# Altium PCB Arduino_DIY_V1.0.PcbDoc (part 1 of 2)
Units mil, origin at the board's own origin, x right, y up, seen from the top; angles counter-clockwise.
Board outline 4006.09 x 4935.69 mil, 2 copper layers (Top Layer, Bottom Layer), stack 46.063 mil thick; 121 components, 93 nets, 429 pads, 83 vias.
Unrouted connection lines stored in the file: 78.
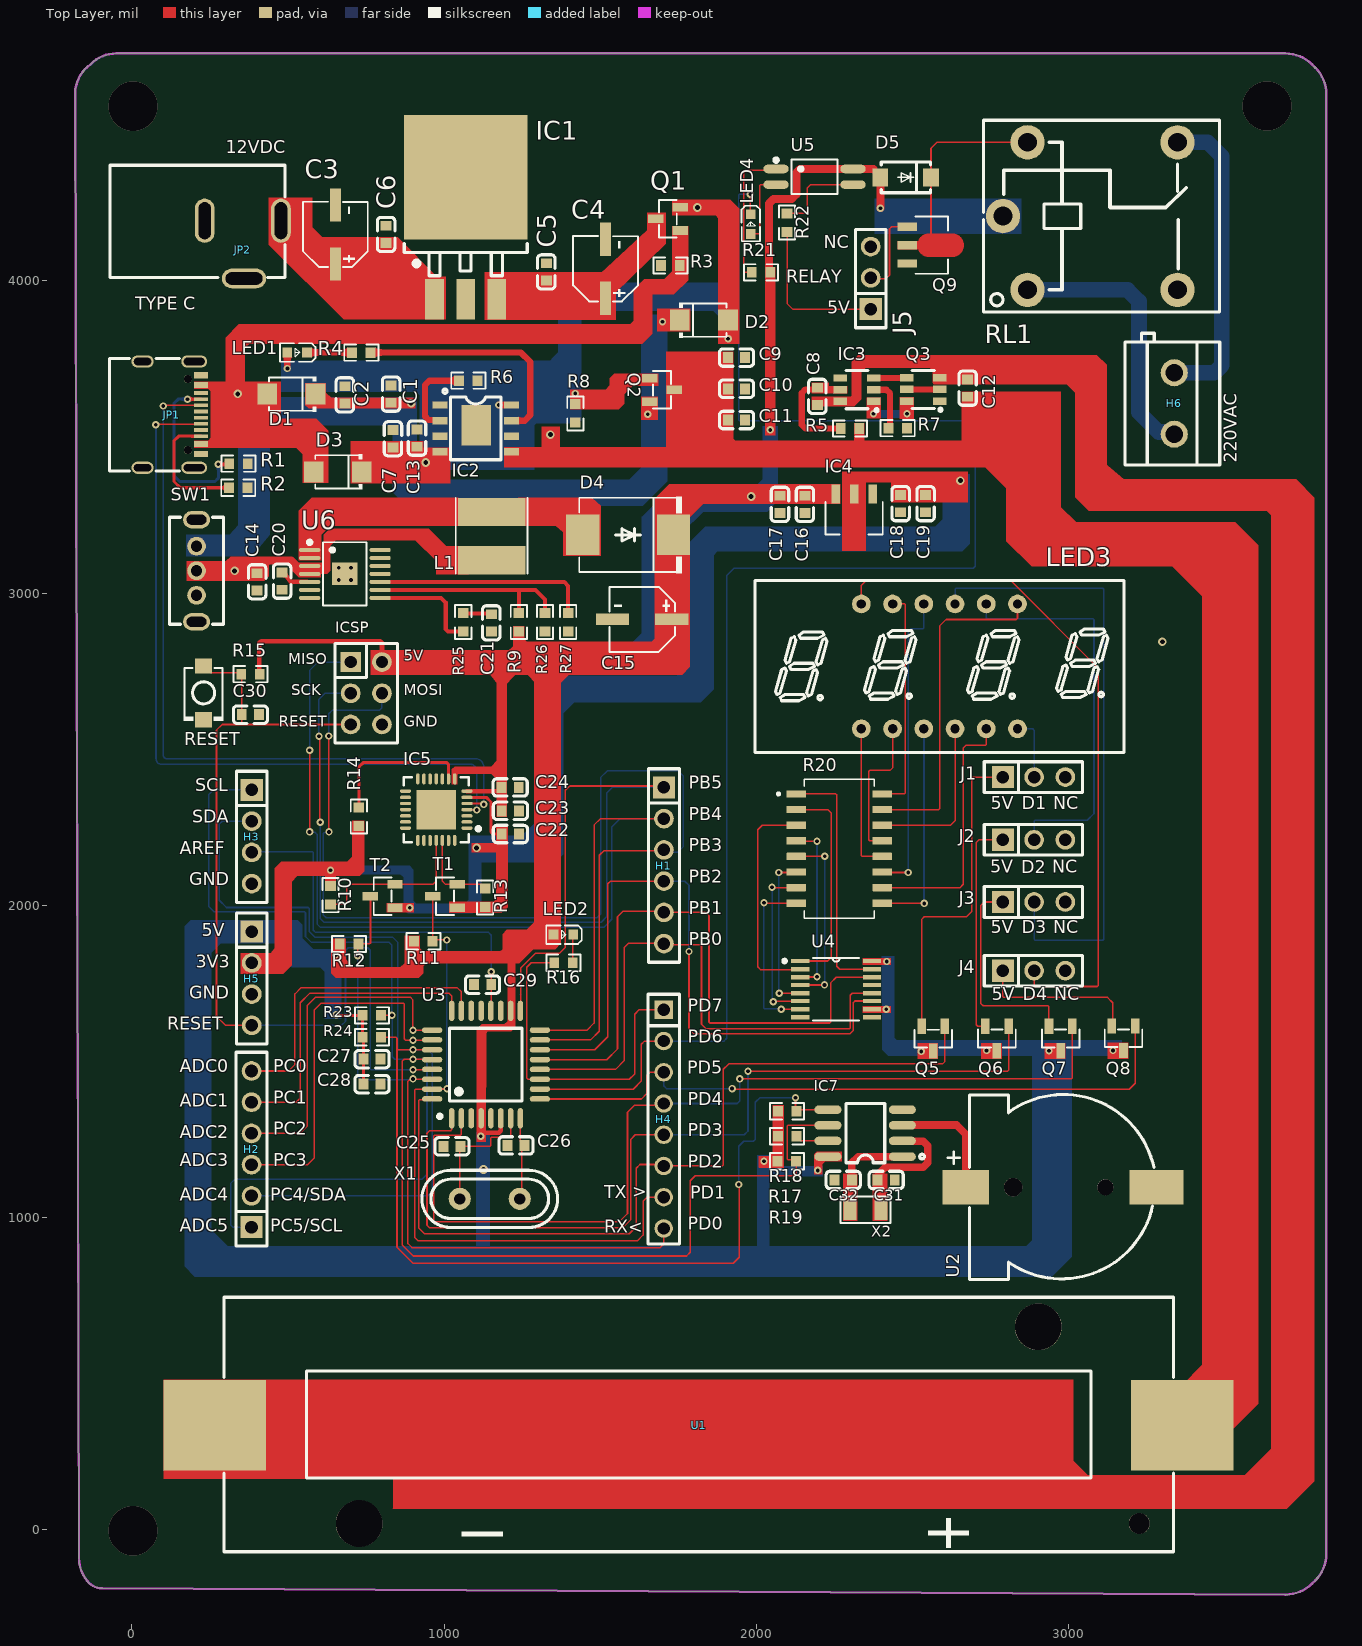
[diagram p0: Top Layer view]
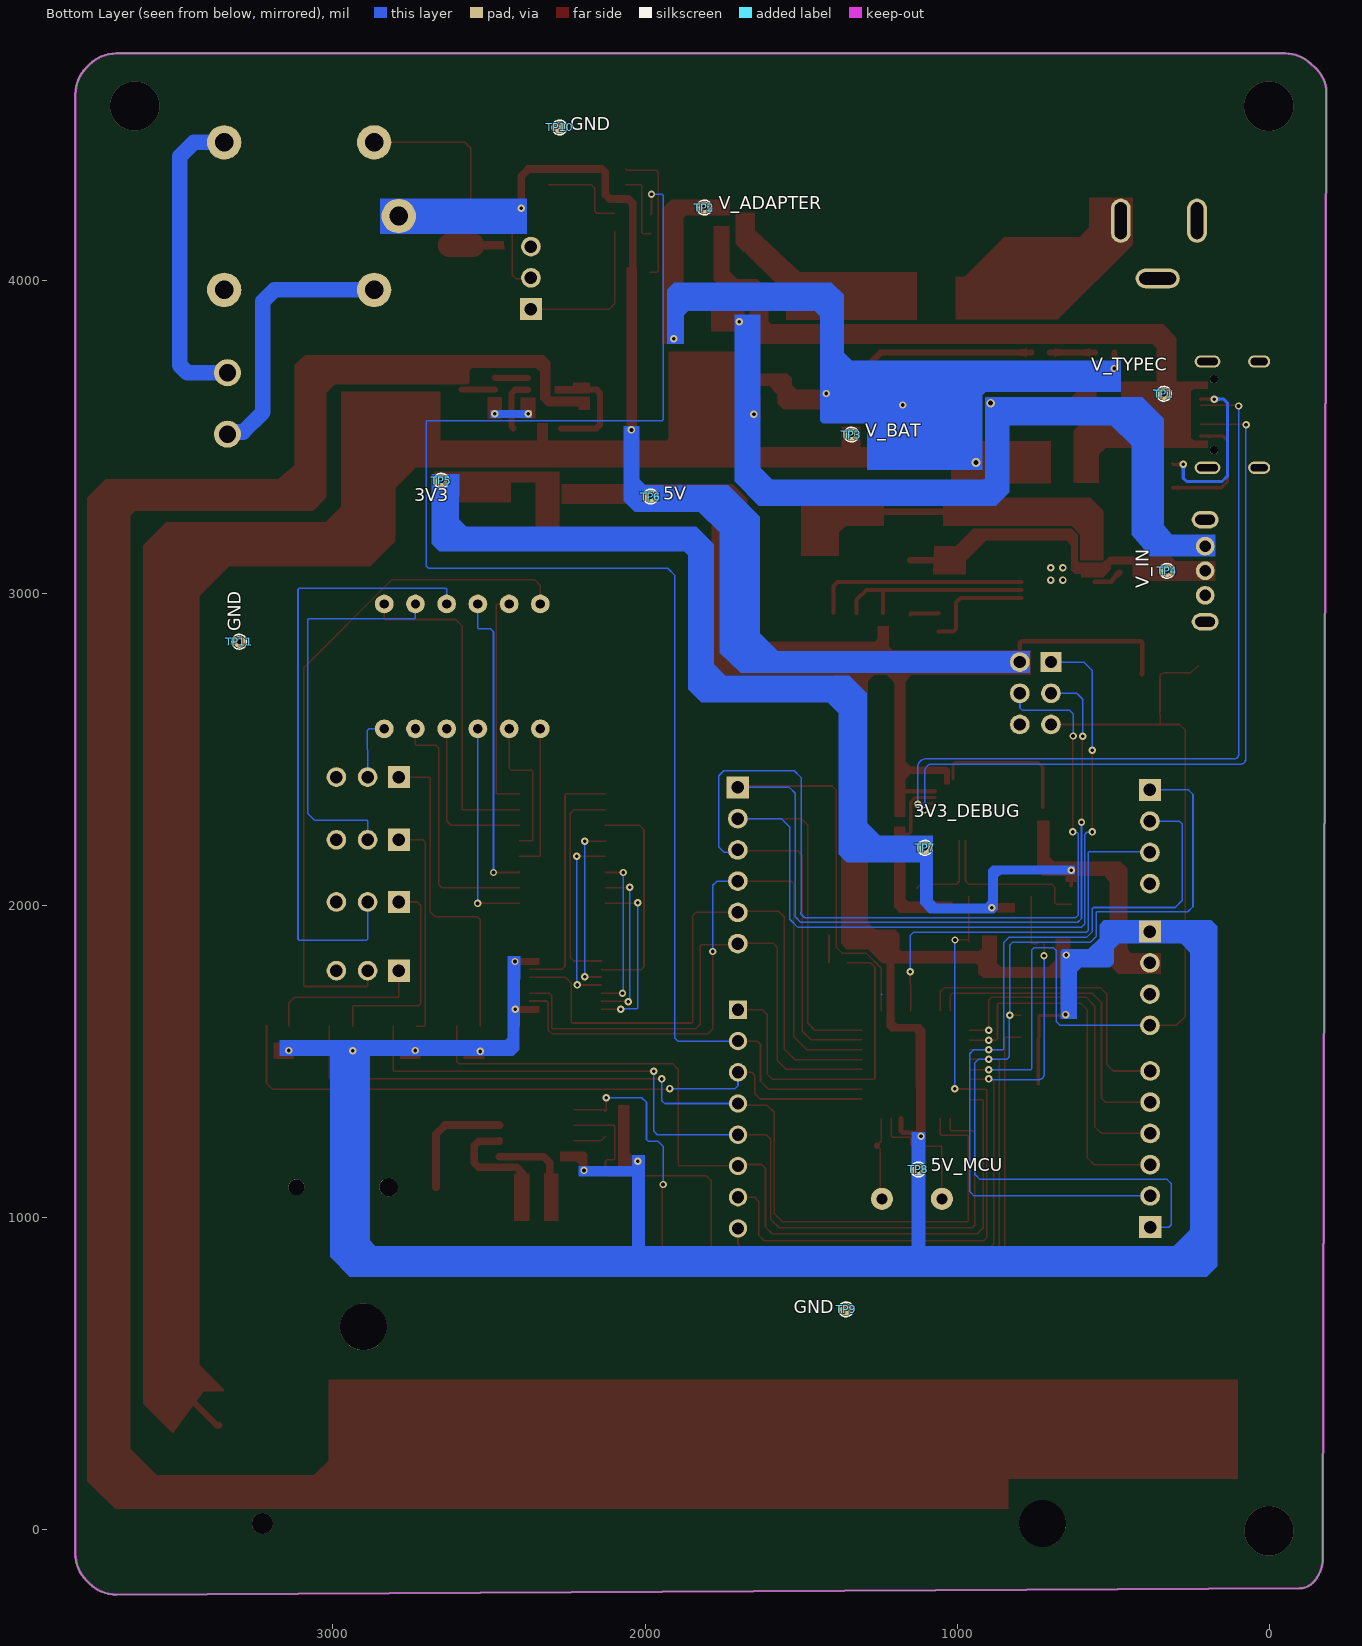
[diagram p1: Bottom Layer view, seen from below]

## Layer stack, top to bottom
Top Solder: solder mask 0.5, Solder Resist, Dk 3.8
Top Layer: signal copper 1.378
Dielectric 1: dielectric 43.307, FR-4, Dk 4.5
Bottom Layer: signal copper 1.378
Bottom Solder: solder mask 0.5, Solder Resist, Dk 3.8

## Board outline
-136.76,-170.5 ccw(c-95.74,-129.48) -95.74,-187.49 3694.03,-207.52 ccw(c3694.03,-86.81) 3779.38,-172.17 3789.67,-161.88 ccw(c3704.32,-76.52) 3825.03,-76.52 3825,-75.9 3825,4597 ccw(c3704.29,4597) 3789.65,4682.35 3779.35,4692.65 ccw(c3694,4607.29) 3694,4728 3608.61,4728 3608.61,4728.17 -49.9,4728.17 ccw(c-49.9,4613.53) -130.96,4694.59 -133.61,4692.28 ccw(c-63.14,4595.96) -181.06,4614.33 -169.44,-91.6 ccw(c-57.87,-91.6)

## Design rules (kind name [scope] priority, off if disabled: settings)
BoardOutlineClearance [All] p1: gap=7.87 ignorepadtopadclearanceinfootprint=FALSE
Clearance [All] p1: gap=5 ignorepadtopadclearanceinfootprint=FALSE except(9.84: Arc-Hole Track-Hole SMDPad-Hole THPad-Hole Via-Hole Fill-Hole Poly-Hole Region-Hole Text-Hole)
ComponentClearance [All] p1: gap=5 collisioncheckmode=3 verticalgap=5 showdistances=TRUE
DiffPairsRouting [All] p1: maxlimit=10 minlimit=5 mostfreqgap=5 toplayer_minwidth=5 toplayer_maxwidth=1000 toplayer_prefwidth=5 bottomlayer_minwidth=5 bottomlayer_maxwidth=1000 bottomlayer_prefwidth=5 maxuncoupledlength=500
Height [All] p1: minheight=0 maxheight=71497.94 prefheight=500
HoleSize [All] p1: absolutevalues=TRUE maxlimit=248.03 minlimit=11.81 maxpercent=80.000 minpercent=20.000
HoleToHoleClearance [All] p1: gap=9.84 allowstackedmicrovias=FALSE
MinimumAnnularRing [All] p1: minimumring=3
MinimumSolderMaskSliver [All] p1: minsoldermaskwidth=0
PlaneClearance [All] p1: clearance=5
PlaneConnect PlaneConnectPowerPads [InPadClass('PowerPads')] p1: planeconnectstyle=Direct reliefexpansion=20 reliefentries=4 reliefconductorwidth=10 reliefairgap=10
PlaneConnect [All] p2: pad.planeconnectstyle=Relief pad.reliefexpansion=11.81 pad.reliefentries=4 pad.reliefconductorwidth=5 pad.reliefairgap=5 via.planeconnectstyle=Direct via.reliefexpansion=11.81 via.reliefentries=4 via.reliefconductorwidth=5 via.reliefairgap=5
PolygonConnect PolygonConnectPowerPads [All vs (InPadClass('PowerPads'))] p1: connectstyle=Direct reliefconductorwidth=10 reliefentries=4 polygonreliefangle="90 Angle" airgapwidth=10
PolygonConnect [All] p2: thpad.connectstyle=Relief thpad.reliefconductorwidth=5 thpad.reliefentries=4 thpad.polygonreliefangle="90 Angle" thpad.airgapwidth=5 smdpad.connectstyle=Relief smdpad.reliefconductorwidth=5 smdpad.reliefentries=4 smdpad.polygonreliefangle="90 Angle" smdpad.airgapwidth=5 via.connectstyle=Direct via.reliefconductorwidth=5 via.reliefentries=4 via.polygonreliefangle="90 Angle" via.airgapwidth=5
RoutingVias [All] p1: holewidth=11.81 width=23.62 viastyle="Through Hole" minholewidth=11.81 minwidth=23.62 maxholewidth=23.62 maxwidth=259.84
SilkToSilkClearance [All] p1: silktosilkclearance=0
SilkToSolderMaskClearance [IsPad] p1: minsilkscreentomaskgap=5 clearancetoexposedcopper=TRUE
SolderMaskExpansion [All] p1: expansion=2.95 istentingtop=FALSE
Width [All] p1: maxlimit=1000 minlimit=5 preferedwidth=5 minimp=50.000000 maximp=50.000000 favimp=50.000000
20 further rules are at their usual default settings.

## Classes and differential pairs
component class "VOLTAGE SOURCE": C1 C2 C3 C4 C5 C6 C7 C8 C9 C10 C11 C12 C13 C14 C15 C16 C17 C18 C19 C20 C21 D1 D2 D3 D4 IC1 IC2 IC3 IC4 JP1 JP2 L1 LED1 Q1 Q2 Q3 R1 R2 R3 R4 R5 R6 R7 R8 R9 R25 R26 R27 SW1 TP1 TP2 TP3 TP4 TP5 TP6 TP9 TP10 TP11 U1 U6 V_IN
component class Peripheral: C31 C32 D5 H1 H2 H3 H4 H5 H6 IC7 ICSP J1 J2 J3 J4 J5 LED3 LED4 Q5 Q6 Q7 Q8 Q9 R17 R18 R19 R20 R21 R22 R23 R24 RL1 U2 U4 U5 X2
component class MCU: C22 C23 C24 C25 C26 C27 C28 C29 C30 IC5 LED2 R10 R11 R12 R13 R14 R15 R16 RESET T1 T2 TP7 TP8 U3 X1

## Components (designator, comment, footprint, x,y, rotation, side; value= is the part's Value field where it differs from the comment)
C1 "100nF" C0603 830,3637 r270 top
C2 "22uF" C0603 681.99,3634.51 r270 top
C3 "47uF, 25V" CAP_ALU_C 652,4148.35 r90 top
C4 "47uF, 25V" CAP_ALU_C 1517,4038.35 r90 top
C5 "100nF" C0603 1327,4028.35 r270 top
C6 "330nF" C0603 814,4148.35 r270 top
C7 "100nF" C0603 836,3494 r270 top
C8 "100nF" C0603 2195,3630 r90 top
C9 "100nF" C0603 1936.22,3753.96 r180 top
C10 "10uF" C0603 1936.22,3653.96 r180 top
C11 "22uF" C0603 1936.22,3553.96 r180 top
C12 "10uF" C0603 2676,3656 r270 top
C13 "10uF" C0603 913,3496 r270 top
C14 "22uF" C0603 401,3036 r90 top
C15 "47uF, 25V" CAP_ALU_C 1634,2916 r180 top
C16 "10uF" C0603 2155.35,3284 r90 top
C17 "22uF" C0603 2075.35,3284 r90 top
C18 "10uF" C0603 2461.65,3286 r90 top
C19 "22uF" C0603 2541.65,3286 r90 top
C20 "47nF" C0603 481,3038 r90 top
C21 "33nF" C0603 1151,2904.5 r90 top
C22 "100nF" C0603 1212,2228.35 r180 top
C23 "100nF" C0603 1212,2302.35 r180 top
C24 "1uF" C0603 1211.44,2377.35 r180 top
C25 "33pF" C0603 1025,1228 r180 top
C26 "33pF" C0603 1230,1231 r180 top
C27 "10uF" C0603 769,1507.35 r180 top
C28 "10nF" C0603 769,1427.35 r180 top
C29 "100nF" C0603 1123,1746 r0 top
C30 "10pF" C0603 379.5,2610.35 r0 top
C31 "33pF" C0603 2415.55,1120.35 r0 top
C32 "33pF" C0603 2278,1120.35 r180 top
D1 "S3MF" D_SMAF_L3.5-W2.6-LS4.7-RD 511,3637 r180 top
D2 "S3MF" D_SMAF_L3.5-W2.6-LS4.7-RD 1832,3874 r0 top
D3 "S3MF" D_SMAF_L3.5-W2.6-LS4.7-RD 659,3388 r180 top
D4 "SS54" SMC 1589,3186 r180 top
D5 "1N4007_M7" SMA(DO-214AC) 2478,4331 r0 top
H1 "6P 2.54mm Female Header" "6P, 2,54mm, FEMALE HEADER" 1703.79,2127.35 r270 top
H2 "6P 2.54mm Female Header" "6P, 2,54mm, FEMALE HEADER" 383,1219.35 r90 top
H3 "4P 2.54mm Female Header" "4P, 2,54mm, FEMALE HEADER" 383.79,2219.35 r270 top
H4 "8P 2.54mm Female Header" "8P, 2,54mm, FEMALE HEADER" 1703,1315.24 r270 top
H5 "4P 2.54mm Female Header" "4P, 2,54mm, FEMALE HEADER" 383.79,1765.52 r270 top
H6 "KF301-5.0-2P" CONN-TH_P5.00_KF301-5.0-2P 3338,3607 r90 top
IC1 "LM7805" TO-263-3L 1071,4332.26 r90 top
IC2 "TP4056" ESOP-8 1102,3525 r270 top
IC3 "DW01A" SOT-23-6 2322,3651 r90 top
IC4 "AMS1117-3.3" SOT-89-3L 2313,3317 r90 top
IC5 "CP2102" WQFN-28-EP(5x5) 974.58,2306.31 r180 top
IC7 "DS1307" SOIC-8 2348,1270.35 r180 top
ICSP "2x3P 2.54mm Female Header" "2x3P, 2.54mm, Female Header" 750.72,2679 r0 top
J1 "JUMPER_SHUNT_3P" JUMPER_SHUNT_3P 2789.16,2410.56 r0 top
J2 "JUMPER_SHUNT_3P" JUMPER_SHUNT_3P 2789.16,2209.78 r0 top
J3 "JUMPER_SHUNT_3P" JUMPER_SHUNT_3P 2789.16,2010.56 r0 top
J4 "JUMPER_SHUNT_3P" JUMPER_SHUNT_3P 2789.16,1790.56 r0 top
J5 "JUMPER_SHUNT_3P" JUMPER_SHUNT_3P 2366,3909.35 r90 top
JP1 "TYPE_C_16P, Female" TYPE_C_16P 128,3571.35 r270 top
JP2 "DC_POWER_JACK" DC_POWER_JACK_6.3mm_2.1mm 233.15,4192.35 r0 top
L1 "4.7uH 3.1A" CD54 1152,3180 r270 top
LED1 "Red" LED0603_RED 529,3770.35 r0 top
LED2 "Blue" LED0603_BLUE 1381.69,1906.04 r0 top
LED3 "LED7SEG" LED7SEG_4 2586,2765 r0 top
LED4 "Green" LED0603_GREEN 1982,4181.35 r90 top
Q1 "AO3401" TF_SOT_23_3 1676.75,4198.35 r90 top
Q2 "AO3401" TF_SOT_23_3 1736.99,3650.4 r270 top
Q3 "FS8205A" TF_SOT23-6 2587.31,3614.6 r180 top
Q5 "ZXTN2031FTA" SOT-23 2566.16,1572.93 r90 top
Q6 "ZXTN2031FTA" SOT-23 2770.16,1573.56 r90 top
Q7 "ZXTN2031FTA" SOT-23 2974.16,1573.56 r90 top
Q8 "ZXTN2031FTA" SOT-23 3175.56,1574.19 r90 top
Q9 "2N2222" SOT-89-3L 2483,4114.06 r180 top
R1 "5.1kΩ" R0603 395.88,3440.36 r180 top
R2 "5.1kΩ" R0603 395.19,3363.01 r180 top
R3 "10kΩ" R0603 1670.12,4022.99 r0 top
R4 "10kΩ" R0603 680.12,3743.99 r0 top
R5 "100Ω" R0603 2245.12,3500.99 r0 top
R6 "2kΩ" R0603 1131.88,3706.01 r180 top
R7 "1kΩ" R0603 2506.88,3554.01 r180 top
R8 "10kΩ" R0603 1446.01,3520.81 r90 top
R9 "49.9kΩ" R0603 1213,2961.22 r270 top
R10 "10kΩ" R0603 662.01,1977.81 r90 top
R11 "10kΩ" R0603 987.88,1911.01 r180 top
R12 "10kΩ" R0603 749.88,1902.01 r180 top
R13 "10kΩ" R0603 1104.99,2079.23 r270 top
R14 "1kΩ" R0603 700.99,2338.54 r270 top
R15 "10kΩ" R0603 325.31,2714.34 r0 top
R16 "330Ω" R0603 1327.51,1790.04 r0 top
R17 "4.7kΩ" R0603 2152.88,1286.36 r180 top
R18 "4.7kΩ" R0603 2152.88,1366.36 r180 top
R19 "4.7kΩ" R0603 2152.19,1206.36 r180 top
R20 "RES_ARRAY_8_RES_330Ω" SOIC-16-5.6mm 2265.16,2181.56 r0 top
R21 "330Ω" R0603 1960.12,4000.99 r0 top
R22 "2kΩ" R0603 2071.99,4240.88 r270 top
R23 "4.7kΩ" R0603 823.19,1673.36 r180 top
R24 "4.7kΩ" R0603 823.19,1603.36 r180 top
R25 "2.55kΩ" R0603 1034.99,2961.22 r270 top
R26 "16.2kΩ" R0603 1349.02,2852.16 r90 top
R27 "133KΩ" R0603 1423.01,2852.16 r90 top
RESET "SMD 3mm×4mm" "ROUND_BUTTON_SMD 3*4mm" 229.5,2680.35 r270 top
RL1 "SRD-05VDC-SL-C" "Through Hole,15.6x19.2mm" 3069,4207 r0 top
SW1 "SK12D07VG4" SK12D07VG4 207,3234.74 r270 top
T1 "BS170F" SOT-23 1003,2029.35 r0 top
T2 "BS170F" SOT-23 803,2029.35 r0 top
TP1 "Test Point" TEST_POINT 339,3638 r90 bottom
TP2 "Test Point" TEST_POINT 1810.82,4234.53 r90 bottom
TP3 "Test Point" TEST_POINT 1340,3507.35 r90 bottom
TP4 "Test Point" TEST_POINT 329,3071 r90 bottom
TP5 "Test Point" TEST_POINT 2653,3360 r180 bottom
TP6 "Test Point" TEST_POINT 1983,3309 r90 bottom
TP7 "Test Point" TEST_POINT 1104,2184 r0 bottom
TP8 "Test Point" TEST_POINT 1126,1154 r270 bottom
TP9 "Test Point" TEST_POINT 1357,706 r90 bottom
TP10 "Test Point" TEST_POINT 2274.58,4490.96 r90 bottom
TP11 "Test Point" TEST_POINT 3300,2844 r180 bottom
U1 "Battery Holder 18650 SMD" PIN_18650_1S_HOLDER_SMD 1815,335 r180 top
U2 "3V_COIN_BATTERY_HOLDER" 3V_COIN_BATERRY_HOLDER_CR1220 2975.54,1097 r180 top
U3 "ATMEGA328P-AU" "TQFP-32 (7x7)" 1134,1490 r90 top
U4 "74HC595" TSSOP16 2255.16,1731.56 r0 top
U5 "TLP291" SO-4 2186,4333 r0 top
U6 "TPS61175PWPR" HTSSOP-14-EP 682,3061 r270 top
X1 "16MHz" HC-49S 1146,1060 r180 top
X2 "32.768kHz" SMD3215-2P 2349,1025 r0 top

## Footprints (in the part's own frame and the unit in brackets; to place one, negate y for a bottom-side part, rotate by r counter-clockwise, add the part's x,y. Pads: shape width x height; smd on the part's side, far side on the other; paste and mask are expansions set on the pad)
"2x3P, 2.54mm, Female Header" [mm]
  rect 1.7x1.6 hole 1 paste-2539.97 mask+0.051: 1(-1.27,2.54)
  round 1.6 hole 1 paste-2539.97 mask+0.051: 2(-1.27,0) 3(-1.27,-2.54) 4(1.27,-2.54) 5(1.27,0) 6(1.27,2.54)
  silkscreen extent -2.54,-4.04 2.54,4.04, body extent -2.5,-4.06 2.5,4.06, height 8.5
3V_COIN_BATERRY_HOLDER_CR1220 [mm]
  rect 3.75x2.8 smd paste+0 mask+0.051: 1(7.75,0)
  rect 4.4x2.8 smd paste+0 mask+0.051: 2(-7.75,0)
  round 1.3 hole 1.3 unplated paste-2539.97: ""(-3.6,0)
  round 1.5 hole 1.5 unplated paste-2539.97: ""(3.9,0)
  silkscreen extent -7.55,-7.54 9.22,7.49, body extent -9.78,-7.4 9.42,7.35, height 4.25
"4P, 2,54mm, FEMALE HEADER" [mm]
  rect 1.8x1.8 hole 1.02 paste-2539.97 mask+0.051: 1(-3.81,0)
  round 1.6 hole 1.02 paste-2539.97 mask+0.051: 2(-1.27,0) 3(1.27,0) 4(3.81,0)
  silkscreen extent -5.33,-1.25 5.33,1.25, body extent -5.08,-1.25 5.08,1.25, height 8.5
"6P, 2,54mm, FEMALE HEADER" [mm]
  rect 1.8x1.8 hole 1.02 paste-2539.97 mask+0.051: 1(-6.35,0)
  round 1.6 hole 1.02 paste-2539.97 mask+0.051: 2(-3.81,0) 3(-1.27,0) 4(1.27,0) 5(3.81,0) 6(6.35,0)
  silkscreen extent -7.87,-1.25 7.87,1.25, body extent -7.62,-1.25 7.62,1.25, height 8.5
"8P, 2,54mm, FEMALE HEADER" [mm]
  rect 1.5x1.5 hole 1 paste-2539.97 mask+0.051: 1(-8.89,0)
  round 1.5 hole 1 paste-2539.97 mask+0.051: 2(-6.35,0) 3(-3.81,0) 4(-1.27,0) 5(1.27,0) 6(3.81,0) 7(6.35,0) 8(8.89,0)
  silkscreen extent -10.16,-1.27 10.16,1.27, body extent -10.16,-1.25 10.16,1.25, height 8.5
C0603 [mm]
  rect 0.8x0.9 smd paste+0 mask+0.051: 1(-0.7,0) 2(0.7,0)
  silkscreen extent -1.39,-0.71 1.39,0.71, body extent -0.8,-0.39 0.8,0.41, height 0.8
CAP_ALU_C [mm]
  rect 2.7x0.91 smd paste+0 mask+0.051: 1(-2.4,0) 2(2.4,0)
  silkscreen extent -2.66,-2.62 2.66,2.65, body extent -3.25,-2.76 3.25,2.76, height 6.15
CD54 [mil]
  rect 90x216.53 smd paste-3937.01 mask+1.97: 1(75,0) 2(-80,0)
  silkscreen extent -124,-115 118,115, body extent -114,-102 114,102, height 177
CONN-TH_P5.00_KF301-5.0-2P [mm]
  round 2.2 hole 1.4 paste-2539.97 mask+0.051: 1(-2.5,0) 2(2.5,0)
  silkscreen extent -5,-3.7 5.71,4, body extent -5,-3.55 5,4.05, height 10
D_SMAF_L3.5-W2.6-LS4.7-RD [mm]
  rect 1.6x1.7 smd paste+0 mask+0.051: 1(-1.96,0.001) 2(1.96,0.001)
  silkscreen extent -2.01,-1.43 1.83,1.42, body extent -2.65,-1.27 2.65,1.27, height 1
DC_POWER_JACK_6.3mm_2.1mm [mm]
  oval 1.6x3.6 hole 1 slot 3 at 90 deg paste-2539.97 mask+0.051: 1(6.2,0) 2(0,0)
  oval 3.6x1.6 hole 1 slot 3 at 0 deg paste-2539.97 mask+0.051: 3(3.2,-4.7)
  silkscreen extent -7.7,-4.64 6.52,4.51, body extent -7.72,-4.95 6.48,4.45, height 11.09
ESOP-8 [mm]
  rect 0.6x1.2 smd paste+0 mask+0.051: 1(-1.956,-2.934) 2(-0.686,-2.934) 3(0.584,-2.934) 4(1.854,-2.934) 5(1.854,2.883) 6(0.584,2.883) 7(-0.686,2.883) 8(-1.956,2.883)
  rect 3.3x2.4 smd paste+0 mask+0.051: 9(-0.305,0)
  silkscreen extent -3.25,-2.7 2.5,2.02, body extent -2.55,-3.1 2.45,3.1, height 1.82
HC-49S [mm]
  round 1.8 hole 0.9 paste+0 mask+0.051: 1(-2.44,0) 2(2.44,0)
  silkscreen extent -5.52,-2.32 5.52,2.33, body extent -5.83,-2.67 5.83,2.67, height 3.99
HTSSOP-14-EP [mm]
  oval 0.343x1.731 smd paste+0 mask+0.051: 1(-1.95,-2.866) 2(-1.3,-2.866) 3(-0.65,-2.866) 4(0,-2.866) 5(0.65,-2.866) 6(1.3,-2.866) 7(1.95,-2.866) 8(1.95,2.866) 9(1.3,2.866) 10(0.65,2.866) 11(0,2.866) 12(-0.65,2.866) 13(-1.3,2.866) 14(-1.95,2.866)
  rect 1.83x2.055 smd paste+0 mask+0.051: 15(0,0)
  silkscreen extent -2.72,-3.02 2.58,1.77, body extent -2.5,-3.2 2.5,3.2, height 1.2
JUMPER_SHUNT_3P [mm]
  rect 1.8x1.8 hole 1.02 paste-2539.97 mask+0.051: 1(0,0)
  round 1.6 hole 1.02 paste-2539.97 mask+0.051: 2(2.54,0) 3(5.08,0)
  silkscreen extent -1.52,-1.25 6.48,1.25, body extent -1.27,-1.27 6.41,1.27, height 8.6
LED7SEG_4 [mil]
  round 60 hole 30: 1(-250,-200) 2(-150,-200) 3(-50,-200) 4(50,-200) 5(150,-200) 6(250,-200) 7(250,200) 8(150,200) 9(50,200) 10(-50,200) 11(-150,200) 12(-250,200)
  silkscreen extent -591,-276 591,276, body extent -591,-276 591,276, height 423
LED0603_BLUE [mm]
  rect 0.8x0.8 smd paste+0 mask+0.051: 1(-0.799,0) 2(0.799,0)
  silkscreen extent -1.39,-0.76 1.49,0.75, body extent -0.8,-0.4 0.8,0.4, height 0.6
LED0603_GREEN [mm]
  rect 0.8x0.8 smd paste+0 mask+0.051: 1(-0.799,0) 2(0.799,0)
  silkscreen extent -1.39,-0.76 1.49,0.75, body extent -0.8,-0.4 0.8,0.4, height 0.6
LED0603_RED [mm]
  rect 0.8x0.8 smd paste+0 mask+0.051: 1(-0.799,0) 2(0.799,0)
  silkscreen extent -1.39,-0.76 1.49,0.75, body extent -0.8,-0.4 0.8,0.4, height 0.6
PIN_18650_1S_HOLDER_SMD [mm]
  rect 8.34x7.35 smd paste+0 mask+0.051: 1(-39.345,0) 2(39.345,0)
  round 1.7 hole 1.7 unplated paste-2539.97: ""(-35.84,8)
  round 3.8 hole 3.8 unplated paste-2539.97: ""(-27.62,-8) ""(27.62,8)
  silkscreen extent -38.61,-10.41 38.61,10.29, body extent -43.22,-10.4 43.22,10.4, height 17.46
R0603 [mil]
  rect 31.75x34.02 smd paste+0 mask+2: 1(24.88,26.01) 2(84.19,26.01)
  silkscreen extent 0,0 109,52, body extent 24,10 86,42, height 18
"ROUND_BUTTON_SMD 3*4mm" [mm]
  rect 1.23x1.36 smd paste+0 mask+0.051: 1(-2.185,0) 2(2.185,0)
  silkscreen extent -2.03,-1.62 2.25,1.62, body extent -2.45,-1.48 2.55,1.47, height 1.96
SK12D07VG4 [mil]
  round 60 hole 36 paste-99999 mask+1.97: 1(84.65,0) 2(163.39,0) 3(242.13,0)
  oval 55.12x86.61 hole 31.5 slot 62.99 at 90 deg paste-99999 mask+1.97: 4(0,0) 4(326.77,0)
  silkscreen extent -8,-87 335,87, body extent -16,-200 345,87, height 138
SMA(DO-214AC) [mil]
  rect 50x57.9 smd paste+0 mask+2: 1(-81,0) 2(81,0)
  silkscreen extent -78,-49 79,49, body extent -102,-57 102,57, height 91
SMC [mm]
  rect 2.7x3.3 smd paste+0 mask+0.051: 1(-3.686,0) 2(3.686,0)
  silkscreen extent -4.36,-3.1 3.98,3.1, body extent -3.97,-2.95 3.97,2.95, height 2.5
SMD3215-2P [mm]
  rect 1.05x1.7 smd paste+0 mask+0.051: 1(-1.27,0) 2(1.27,0)
  silkscreen extent -2.03,-1.08 2.03,1.08, body extent -1.65,-0.8 1.65,0.8, height 0.89
SO-4 [mm]
  oval 2.056x0.7 smd paste+0 mask+0.051: 1(-3.128,0.635) 2(-3.128,-0.635) 3(3.128,-0.635) 4(3.128,0.635)
  silkscreen extent -3.28,-1.4 1.87,1.5, body extent -3.5,-1.42 3.5,1.42, height 2.21
SOIC-8 [mm]
  oval 2.2x0.7 smd paste+0 mask+0.051: 1(-3.023,1.905) 2(-3.023,0.635) 3(-3.023,-0.635) 4(-3.023,-1.905) 5(3.023,-1.905) 6(3.023,-0.635) 7(3.023,0.635) 8(3.023,1.905)
  silkscreen extent -4.82,-2.41 1.55,2.41, body extent -2.95,-2.45 2.95,2.45, height 1.52
SOIC-16-5.6mm [mm]
  rrect15% 1.59x0.6 smd: 1(-3.495,4.445) 2(-3.495,3.175) 3(-3.495,1.905) 4(-3.495,0.635) 5(-3.495,-0.635) 6(-3.495,-1.905) 7(-3.495,-3.175) 8(-3.495,-4.445) 9(3.495,-4.445) 10(3.495,-3.175) 11(3.495,-1.905) 12(3.495,-0.635) 13(3.495,0.635) 14(3.495,1.905) 15(3.495,3.175) 16(3.495,4.445)
  silkscreen extent -5.04,-5.65 2.86,5.65, body extent -3.81,-5.59 3.81,5.59, height 2.4
SOT-23 [mm]
  rect 1.25x0.7 smd: 1(1,-0.95) 2(1,0.95) 3(-1,0)
  silkscreen extent -0.73,-1.53 0.73,1.53, body extent -1.25,-1.5 1.25,1.5, height 1.1
SOT-23-6 [mm]
  rect 0.6x1.1 smd paste+0 mask+0.051: 1(-0.95,-1.35) 2(0,-1.35) 3(0.95,-1.35) 4(0.95,1.35) 5(0,1.35) 6(-0.95,1.35)
  silkscreen extent -1.79,-1.72 1.55,0.9, body extent -1.46,-1.6 1.46,1.6, height 1.14
SOT-89-3L [mm]
  rect 1.575x0.672 smd paste+0 mask+0.051: 1(0,-1.5) 2(0,0) 3(0,1.5)
  Top Layer region: -3.64,0.959 -1.785,0.959 -1.741,0.958 -1.696,0.955 -1.652,0.949 -1.608,0.942 -1.565,0.933 -1.522,0.921 -1.479,0.908 -1.437,0.893 -1.396,0.875 -1.356,0.856 -1.317,0.835 -1.279,0.812 -1.241,0.788 -1.206,0.761 -1.171,0.733 -1.138,0.704 -1.106,0.673 -1.075,0.64 -1.047,0.606 -1.019,0.571 -0.994,0.534 -0.97,0.496 -0.948,0.458 -0.928,0.418 -0.91,0.339 0.788,0.339 0.775,-0.33 -0.901,-0.336 -0.928,-0.401 -0.948,-0.44 -0.97,-0.479 -0.994,-0.517 -1.019,-0.553 -1.047,-0.589 -1.075,-0.623 -1.106,-0.655 -1.138,-0.686 -1.171,-0.716 -1.206,-0.744 -1.241,-0.77 -1.279,-0.795 -1.317,-0.818 -1.356,-0.839 -1.396,-0.858 -1.437,-0.875 -1.479,-0.891 -1.522,-0.904 -1.565,-0.915 -1.608,-0.925 -1.652,-0.932 -1.696,-0.937 -1.741,-0.94 -1.785,-0.941 -3.64,-0.941 -3.684,-0.94 -3.728,-0.937 -3.773,-0.932 -3.817,-0.925 -3.86,-0.915 -3.903,-0.904 -3.946,-0.891 -3.988,-0.875 -4.029,-0.858 -4.069,-0.839 -4.108,-0.818 -4.146,-0.795 -4.183,-0.77 -4.219,-0.744 -4.254,-0.716 -4.287,-0.686 -4.319,-0.655 -4.349,-0.623 -4.378,-0.589 -4.405,-0.553 -4.431,-0.517 -4.455,-0.479 -4.477,-0.44 -4.497,-0.401 -4.515,-0.36 -4.531,-0.319 -4.546,-0.276 -4.558,-0.234 -4.568,-0.19 -4.577,-0.147 -4.583,-0.102 -4.587,-0.058 -4.589,-0.014 -4.589,0.031 -4.587,0.075 -4.583,0.12 -4.577,0.164 -4.568,0.208 -4.558,0.251 -4.546,0.294 -4.531,0.336 -4.515,0.377 -4.497,0.418 -4.477,0.458 -4.455,0.496 -4.431,0.534 -4.405,0.571 -4.378,0.606 -4.349,0.64 -4.319,0.673 -4.287,0.704 -4.254,0.733 -4.219,0.761 -4.183,0.788 -4.146,0.812 -4.108,0.835 -4.069,0.856 -4.029,0.875 -3.988,0.893 -3.946,0.908 -3.903,0.921 -3.86,0.933 -3.817,0.942 -3.773,0.949 -3.728,0.955 -3.684,0.958
  silkscreen extent -3.31,-2.33 -0.65,2.33, body extent -3.88,-2.25 0.37,2.25, height 1.54
TEST_POINT [mm]
  round 1 smd: 1(0,0)
  silkscreen extent -0.6,-0.6 0.6,0.6
TF_SOT23-6 [mm]
  rect 1.1x0.6 smd paste+0 mask+0.051: 1(0,0) 2(0,-0.95) 3(0,-1.9) 4(2.7,-1.9) 5(2.7,-0.95) 6(2.7,0)
  silkscreen extent -0.17,-2.5 2.25,0.83, body extent 0.12,-2.44 2.62,0.56, height 1.1
TF_SOT_23_3 [mm]
  rect 0.7x1.25 smd paste+0 mask+0.051: 1(-0.95,-2.006) 2(0.95,-2.006) 3(0,-0.006)
  silkscreen extent -1.53,-1.73 1.53,-0.28, body extent -1.52,-2.29 1.47,0.21, height 1.1
"Through Hole,15.6x19.2mm" [mil]
  round 110 hole 60 paste-99999 mask+2: 1(-200.79,-236.22) 2(279.53,-236.2) 3(279.53,236.2) 4(-200.79,236.22) 5(-279.53,0)
  silkscreen extent -342,-307 413,307, body extent -338,-302 418,312, height 622
TO-263-3L [mil]
  rect 129.92x59.49 smd paste+0 mask+2: 1(-390.91,102) 2(-390.91,2) 3(-390.91,-98)
  rect 398.5x394.49 smd paste+0 mask+2: 4(-1,2)
  silkscreen extent -316,-195 -214,199, body extent -440,-192 176,202, height 189
"TQFP-32 (7x7)" [mm]
  oval 1.65x0.45 smd paste+0 mask+0.051: 1(-4.369,2.8) 2(-4.369,2) 3(-4.369,1.2) 4(-4.369,0.4) 5(-4.369,-0.4) 6(-4.369,-1.2) 7(-4.369,-2) 8(-4.369,-2.8) 17(4.369,-2.8) 18(4.369,-2) 19(4.369,-1.2) 20(4.369,-0.4) 21(4.369,0.4) 22(4.369,1.2) 23(4.369,2) 24(4.369,2.8)
  oval 0.45x1.65 smd paste+0 mask+0.051: 9(-2.8,-4.381) 10(-2,-4.381) 11(-1.2,-4.381) 12(-0.4,-4.381) 13(0.4,-4.381) 14(1.2,-4.381) 15(2,-4.381) 16(2.8,-4.381) 25(2.8,4.382) 26(2,4.382) 27(1.2,4.382) 28(0.4,4.382) 29(-0.4,4.382) 30(-1.2,4.382) 31(-2,4.382) 32(-2.8,4.382)
  silkscreen extent -4.36,-2.94 2.95,3.91, body extent -4.5,-4.5 4.5,4.5, height 0.53
TSSOP16 [mil]
  rect 58x14 smd: 1(-115,90) 2(-115,64) 3(-115,38) 4(-115,13) 5(-115,-13) 6(-115,-38) 7(-115,-64) 8(-115,-90) 9(115,-90) 10(115,-64) 11(115,-38) 12(115,-13) 13(115,13) 14(115,38) 15(115,64) 16(115,90)
  silkscreen extent -171,-100 74,100, body extent -126,-98 126,98, height 43
TYPE_C_16P [mm]
  oval 1x2.1 hole 0.6 slot 1.7 at 90 deg paste-2539.97 mask+0.051: 17(-4.32,1.816) 20(4.32,1.816)
  oval 1x1.8 hole 0.6 slot 1.4 at 90 deg paste-2539.97 mask+0.051: 18(-4.32,-2.384) 19(4.32,-2.384)
  rect 0.3x1.14 smd paste+0 mask+0.051: A5(-1.25,2.383) A6(-0.25,2.383) A7(0.25,2.383) A8(1.25,2.384) B5(1.75,2.383) B6(0.75,2.383) B7(-0.75,2.383) B8(-1.75,2.384)
  rect 0.5x1.14 smd paste+0 mask+0.051: A9B4(2.4,2.383) A12B1(3.2,2.383) B9A4(-2.4,2.383) B12A1(-3.2,2.383)
  round 0.65 hole 0.65 unplated paste-2539.97: ""(-2.89,1.296) ""(2.89,1.296)
  silkscreen extent -4.57,-5.08 4.57,0.63, body extent -4.45,-4.7 4.45,2.86, height 3.25
WQFN-28-EP(5x5) [mm]
  oval 0.9x0.28 smd paste+0 mask+0.051: 1(-2.5,1.501) 2(-2.5,1.001) 3(-2.5,0.501) 4(-2.5,0) 5(-2.5,-0.5) 6(-2.5,-1.001) 7(-2.5,-1.501) 15(2.5,-1.501) 16(2.5,-1.001) 17(2.5,-0.5) 18(2.5,0) 19(2.5,0.501) 20(2.5,1.001) 21(2.5,1.501)
  oval 0.28x0.9 smd paste+0 mask+0.051: 8(-1.501,-2.5) 9(-1.001,-2.5) 10(-0.501,-2.5) 11(0,-2.5) 12(0.5,-2.5) 13(1.001,-2.5) 14(1.501,-2.5) 22(1.501,2.5) 23(1.001,2.5) 24(0.5,2.5) 25(0,2.5) 26(-0.501,2.5) 27(-1.001,2.5) 28(-1.501,2.5)
  rect 3.2x3.2 smd paste+0 mask+0.051: 29(0,0)
  silkscreen extent -3.58,-2.65 2.65,2.65, body extent -2.58,-2.58 2.58,2.58, height 0.92

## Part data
C1 C5 C7 C8 C9 C22 C23 C29: library part C0603_MLCC_100nF_X7R_50V, "50V 100nF X7R ±10% 0603 Multilayer Ceramic Capacitors MLCC - SMD/SMT ROHS", LCSC Part=C14663, Manufacturer=YAGEO, Mfr. Part=CC0603KRX7R9BB104, Package=0603, Temperature Coefficient="X7R, 50V", Tolerance=±10%, Voltage Rating=50V
C2 C17 C19: library part C0603_MLCC_22uF_X5R_6.3V, "6.3V 22uF X5R ±20% 0603 Multilayer Ceramic Capacitors MLCC - SMD/SMT ROHS", LCSC Part=C109448, Manufacturer=YAGEO, Mfr. Part=CC0603MRX5R5BB226, Package=0603, Temperature Coefficient="X5R, 6.3V", Tolerance=±20%, Voltage Rating=6.3V
C3 C4 C15: library part C_ALU_47uF_25V_C, "25V ±20% 47uF SMD,D5xL6.1mm Hybrid Aluminum Electrolytic Capacitors ROHS", Capacitance=47uF, LCSC Part=C542300, Manufacturer=PANASONIC, Mfr. Part=EEHZK1E470R, Package=C, Tolerance=±20%, Voltage Rating=25V
C6: library part C0603_MLCC_330nF_X7R_25V, "25V 330nF X7R ±10% 0603 Multilayer Ceramic Capacitors MLCC - SMD/SMT ROHS", LCSC Part=C107070, Manufacturer=YAGEO, Mfr. Part=CC0603KRX7R8BB334, Package=0603, Temperature Coefficient="X7R, 25V", Tolerance=±10%, Voltage Rating=25V
C10 C12 C13 C16 C18 C27: library part C0603_MLCC_10uF_X5R_25V, "25V 10uF X5R ±20% 0603 Multilayer Ceramic Capacitors MLCC - SMD/SMT ROHS", LCSC Part=C596327, Manufacturer=YAGEO, Mfr. Part=CC0603MRX5R8BB106, Package=0603, Temperature Coefficient="X5R, 25V", Tolerance=±20%, Voltage Rating=25V
C11 C14: library part C0603_MLCC_22uF_X5R_10V, "10V 22uF X5R ±20% 0603 Multilayer Ceramic Capacitors MLCC - SMD/SMT ROHS", LCSC Part=C86295, Manufacturer="Samsung Electro-Mechanics", Mfr. Part=CL10A226MP8NUNE, Package=0603, Temperature Coefficient="X5R, 10V", Tolerance=±20%, Voltage Rating=10V
C20: library part C0603_MLCC_47nF_X7R_50V, "50V 47nF X7R ±10% 0603 Multilayer Ceramic Capacitors MLCC - SMD/SMT ROHS", LCSC Part=C107093, Manufacturer=YAGEO, Mfr. Part=CC0603KRX7R9BB473, Package=0603, Temperature Coefficient="X7R, 50V", Tolerance=±10%, Voltage Rating=50V
C21: library part C0603_MLCC_33nF_X7R_50V, "50V 33nF X7R ±10% 0603 Multilayer Ceramic Capacitors MLCC - SMD/SMT ROHS", LCSC Part=C106856, Manufacturer=YAGEO, Mfr. Part=CC0603KRX7R9BB333, Package=0603, Temperature Coefficient="X7R, 50V", Tolerance=±10%, Voltage Rating=50V
C24: library part C0603_MLCC_1uF_X7R_50V, "50V 1uF X7R ±10% 0603 Multilayer Ceramic Capacitors MLCC - SMD/SMT ROHS", LCSC Part=C559769, Manufacturer=YAGEO, Mfr. Part=CC0603KRX7R9BB105, Package=0603, Temperature Coefficient="X7R, 50V", Tolerance=±10%, Voltage Rating=50V
C25 C26 C31 C32: library part C0603_MLCC_33pF_NP0_50V, "50V 33pF NP0 ±5% 0603 Multilayer Ceramic Capacitors MLCC - SMD/SMT ROHS", LCSC Part=C107047, Manufacturer=YAGEO, Mfr. Part=CC0603JRNPO9BN330, Package=0603, Temperature Coefficient="NP0, 50V", Tolerance=±5%, Voltage Rating=50V
C28: library part C0603_MLCC_10nF_X7R_50V, "50V 10nF X7R ±10% 0603 Multilayer Ceramic Capacitors MLCC - SMD/SMT ROHS", LCSC Part=C100042, Manufacturer=YAGEO, Mfr. Part=CC0603KRX7R9BB103, Package=0603, Temperature Coefficient="X7R, 50V", Tolerance=±10%, Voltage Rating=50V
C30: library part C0603_MLCC_10pF_NP0_50V, "50V 10pF NP0 ±5% 0603 Multilayer Ceramic Capacitors MLCC - SMD/SMT ROHS", LCSC Part=C106245, Manufacturer=YAGEO, Mfr. Part=CC0603JRNPO9BN100, Package=0603, Temperature Coefficient="NP0, 50V", Tolerance=±5%, Voltage Rating=50V
D1 D2 D3: "3A Independent Type 1.1V@3A 1kV SMAF Diodes - General Purpose ROHS", Manufacturer="Shandong Jingdao Microelectronics", Package=SMAF
D4: "40V Independent 550mV@5A 5A SMC Schottky Diodes ROHS", Manufacturer=TWGMC, Package=SMC, Voltage - Forward(Vf@If)=550mV@5A
D5: "1A 1V@1A 1kV SMA Diodes - General Purpose ROHS", LCSC Part=C20754788, Manufacturer=JSMSEMI, Mfr. Part="1N4007 M7", Package=SMA
H1 H2: "2.54mm 1 6P Through Hole 1x6P Through Hole,P=2.54mm Female Headers ROHS", LCSC Part=C40877, Manufacturer="BOOMELE(Boom Precision Elec)", Mfr. Part=2.54-1*6P, Package="Through Hole,P{}2.54mm"
H3 H5: "2.54mm 1 3A 4P Bronze -40℃~+105℃ Through Hole 1x4P Top Square Hole Through Hole,P=2.54mm Female Headers ROHS", LCSC Part=C2718488, Manufacturer="BOOMELE(Boom Precision Elec)", Mfr. Part=2.54-1*4P, Package="Through Hole,P{}2.54mm"
H4: "2.54mm 1 8P Through Hole 1x8P Through Hole,P=2.54mm Female Headers ROHS", LCSC Part=C27438, Manufacturer="BOOMELE(Boom Precision Elec)", Mfr. Part=2.54-1*8P, Package="Through Hole,P{}2.54mm"
H6: "1x2P -30℃~+120℃ 17A 250V Blue 14~22 Through Hole 5mm 1.5 1 2 Through Hole,P=5mm Screw Terminal Blocks ROHS", Color=Blue, LCSC Part=C474881, Manufacturer="Cixi Kefa Elec", Package="Through Hole,P{}5mm"
IC1: library part LM7805_TO-263-3L, "62dB@(120Hz) 1A Fixed 4.8V~5.2V Positive 35V TO-263-3L Voltage Regulators - Linear, Low Drop Out (LDO) Regulators ROHS", LCSC Part=C5145372, Manufacturer="HANSCHIP semiconductor", Mfr. Part=LM7805SRG, Operating Temperature=-40℃~+85℃@(Ta), Output Current=1A, Output Voltage=4.8V~5.2V, Package=TO-263-3L, Voltage - Supply=35V
IC2: library part TP4056_ESOP-8, "4V~6V Lithium-ion/Polymer 1 ESOP-8 Battery Management ROHS", Charging Saturation Voltage=4.2V, LCSC Part=C382139, Manufacturer=TPOWER, Operating Temperature=-40℃~+85℃, Package=ESOP-8, Voltage - Supply=4V~6V
IC3: "1.5V~8V Lithium-ion/Polymer 1 SOT-23-6 Battery Management ROHS", Charging Saturation Voltage=4.3V, LCSC Part=C2927799, Manufacturer=YONGYUTAI, Operating Temperature=-40℃~+85℃, Package=SOT-23-6, Voltage - Supply=1.5V~8V
IC4: library part AMS1117-3.3_SOT-89-3L, "1A Fixed 3.3V Positive 15V SOT-89-3L Voltage Regulators - Linear, Low Drop Out (LDO) Regulators ROHS", LCSC Part=C5345982, Manufacturer="HXY MOSFET", Operating Temperature=0℃~+125℃@(Ta), Output Current=1A, Output Voltage=3.3V, Package=SOT-89-3L, Voltage - Supply=16V, Voltage Dropout=12mV@(1A)
IC5: "12Mbps Transceiver WQFN-28-EP(5x5) USB Converters ROHS", LCSC Part=C6568, Manufacturer="SILICON LABS", Mfr. Part=CP2102-GMR, Package=WQFN-28-EP(5x5), Voltage - Supply=3V~3.6V
IC7: library part DS1307-SOIC8, "I2C SOIC-8 Real Time Clocks ROHS", LCSC Part=C9868, Manufacturer=MAXIM, Mfr. Part=DS1307Z+T&R, Package=SOIC-8
ICSP: "2.54mm 2.54mm 3A 2 6P -40℃~+105℃ Through Hole 2x3P Top Square Hole Through Hole,P=2.54mm Female Headers ROHS", LCSC Part=C18723054, Manufacturer=HanElectricity, Mfr. Part=2541FV-2x3P, Package="Through Hole,P{}2.54mm"
J1 J2 J3 J4 J5: "250V 3A Through Hole Pin Header 2.5mm 3P 6mm -40℃~+105℃ 3mm 2.54mm 1 Black 1x3P Through Hole,P=2.54mm Pin Headers ROHS", LCSC Part=C2937625, Manufacturer=XFCN, Mfr. Part=PZ254V-11-03P, Package="Through Hole,P{}2.54mm"
JP1: library part TYPE_C_16P, "3A USB 3.1 1 Surface Mount, Right Angle 16P Female -40℃~+85℃ Type-C SMD USB Connectors ROHS", Current Rating-Power=3A, LCSC Part=C7507405, Manufacturer="SHOU HAN", Mfr. Part=TYPE-C-3.1-16PIN, Operating Temperature=-40℃~+85℃, Package=SMD
JP2: library part DC_POWER_JACK_6.3mm_2.1mm, "Right Angle DC Power Jack -40℃~+85℃ 2.1mm 6.3mm 3A 500V Through Hole DC Power Connectors ROHS", Current Rating=3A, LCSC Part=C7498153, Manufacturer="Lian Xin Technology", Mfr. Part=XDJK-0051-025, Operating Temperature=-40℃~+85℃, Package="Through Hole", Voltage Rating (Max)=500V
L1: library part CD54_4.7uH_3.1A, "3.1A 4.7uH ±20% SMD,5.8x5.2mm Power Inductors ROHS", Current=3.1A, Inductor=4.7uH, Manufacture Part Number=CD54-4R7M, Manufacturer=Ceaiya, Package=CD54
LED1: library part LED0603_Red, "20mA 230mcd Water Clear -40℃~+85℃ 630nm Red 120° 75mW 1.95V 0603 LED Indication - Discrete ROHS", Forward Current=20mA, LCSC Part=C5875723, Manufacturer=Kingbright, Mfr. Part=APT1608SURCK, Operating Temperature=-40℃~+85℃, Package=0603, Power(Watts)=75mW, Voltage - Forward(Vf)=1.95V
LED2: library part LED0603_Blue, "2mA 24mcd Water Clear -40℃~+85℃ 470nm Blue 130° 120mW 2.65V 0603 LED Indication - Discrete ROHS", Forward Current=2mA, LCSC Part=C5200747, Manufacturer=Kingbright, Mfr. Part=APT1608LVBC/D, Operating Temperature=-40℃~+85℃, Package=0603, Power(Watts)=120mW, Voltage - Forward(Vf)=2.65V
LED3: library part LED7SEG_Common_Anode, "Red 4 Common Anode 0.56 Through Hole LED Segment Displays ROHS", Illumination Color=Red, LCSC Part=C10713, Manufacturer=ZHIHAO, Mfr. Part=FJ5461BH, Package="Through Hole"
LED4: library part LED0603_Green, "2mA 20mcd~50mcd Water Clear 525nm -40℃~+85℃ Green 130° 75mW 2.65V 0603 LED Indication - Discrete ROHS", Forward Current=2mA, LCSC Part=C598356, Manufacturer=Kingbright, Mfr. Part=KPT-1608LVZGCK, Operating Temperature=-40℃~+85℃, Package=0603, Power(Watts)=75mW, Voltage - Forward(Vf)=2.65V
Q1 Q2: "30V 4.2A 42mΩ@10V,4A 1.4W 800mV@250uA 1 Piece P-Channel SOT-23 MOSFETs ROHS", Continuous Drain Current (Id)=4.2A, Drain Source Voltage (Vdss)=30V, Manufacturer=ElecSuper, Package=SOT-23-3, Power Dissipation (Pd)=1.4W
Q3: "20V 25mΩ@2.5V,3A 1.5W 500mV SOT-23-6 MOSFETs ROHS", Drain to Source Voltage=20V, Gate Threshold Voltage (Vgs(th)@Id)=500mV, Manufacturer="TECH PUBLIC", Package=SOT-23-6
Q5 Q6 Q7 Q8: "50V 200@2A,2V 1.2W 5A NPN SOT-23 Bipolar (BJT) ROHS", Current - Collector(Ic)=5A, LCSC Part=C92166, Manufacturer=DIODES, Operating Temperature=-55℃~+150℃, Package=SOT-23, Pd - Power Dissipation=1.2W, Transition frequency(fT)=125MHz
Q9: library part 2N2222_SOT-89, "40V 500mW 600mA NPN SOT-89 Bipolar (BJT) ROHS", Current - Collector(Ic)=600mA, LCSC Part=C21714170, Manufacturer=CBI, Mfr. Part=2N2222AU, Package=SOT-89, Pd - Power Dissipation=500mW, Transition frequency(fT)=300MHz
R1 R2: library part R0603_5.1kΩ_±1%, "100mW Thick Film Resistor 75V ±100ppm/℃ ±1% 5.1kΩ 0603 Chip Resistor - Surface Mount ROHS", LCSC Part=C105580, Manufacturer=YAGEO, Mfr. Part=RC0603FR-075K1L, Operating Temperature=-55℃~+155℃, Package=0603, Power(Watts)=100mW, Tolerance=±1%
R3 R4 R8 R10 R11 R12 R13 R15: library part R0603_10kΩ_±1%, "100mW Thick Film Resistor 75V ±100ppm/℃ ±1% 10kΩ 0603 Chip Resistor - Surface Mount ROHS", LCSC Part=C98220, Manufacturer=YAGEO, Mfr. Part=RC0603FR-0710KL, Operating Temperature=-55℃~+155℃, Package=0603, Tolerance=±1%
R5: library part R0603_100Ω_±1%, "100mW Thick Film Resistor 75V ±100ppm/℃ ±1% 100Ω 0603 Chip Resistor - Surface Mount ROHS", LCSC Part=C845629, Manufacturer=YAGEO, Mfr. Part=RC0603FR-13100RL, Operating Temperature=-55℃~+155℃, Package=0603, Tolerance=±1%
R6 R22: library part R0603_2kΩ_±1%, "100mW Thick Film Resistor 75V ±100ppm/℃ ±1% 2kΩ 0603 Chip Resistor - Surface Mount ROHS", LCSC Part=C105576, Manufacturer=YAGEO, Mfr. Part=RC0603FR-072KL, Operating Temperature=-55℃~+155℃, Package=0603, Tolerance=±1%
R7 R14: library part R0603_1kΩ_±1%, "100mW Thick Film Resistor 75V ±100ppm/℃ ±1% 1kΩ 0603 Chip Resistor - Surface Mount ROHS", LCSC Part=C22548, Manufacturer=YAGEO, Mfr. Part=RC0603FR-071KL, Operating Temperature=-55℃~+155℃, Package=0603, Tolerance=±1%
R9: library part R0603_49.9KΩ_±1%, "100mW Thick Film Resistor 75V ±100ppm/℃ ±1% 49.9kΩ 0603 Chip Resistor - Surface Mount ROHS", LCSC Part=C114624, Manufacturer=YAGEO, Mfr. Part=RC0603FR-0749K9L, Operating Temperature=-55℃~+155℃, Package=0603, Tolerance=±1%
R16 R21: library part R0603_330Ω_±1%, "100mW Thick Film Resistor 75V ±100ppm/℃ ±1% 330Ω 0603 Chip Resistor - Surface Mount ROHS", LCSC Part=C105881, Manufacturer=YAGEO, Mfr. Part=RC0603FR-07330RL, Operating Temperature=-55℃~+155℃, Package=0603, Tolerance=±1%
R17 R18 R19 R23 R24: library part R0603_4.7kΩ_±1%, "100mW Thick Film Resistor 75V ±100ppm/℃ ±1% 4.7kΩ 0603 Chip Resistor - Surface Mount ROHS", LCSC Part=C99782, Manufacturer=YAGEO, Mfr. Part=RC0603FR-074K7L, Operating Temperature=-55℃~+155℃, Package=0603, Tolerance=±1%
R20: "8 ±2% 330Ω 160mW ±100ppm/℃ SOIC-16-5.6mm Resistor Networks, Arrays ROHS", Manufacturer=BOURNS, Number of Resistors=8, Package=SOIC-16-5.6mm, Resistance=330Ω, Tolerance=±2%
R25: library part R0603_2.55KΩ_±0.1%, "100mW Thin Film Resistor 75V ±25ppm/℃ ±0.1% 2.55kΩ 0603 Chip Resistor - Surface Mount ROHS", LCSC Part=C326728, Manufacturer=YAGEO, Mfr. Part=RT0603BRD072K55L, Operating Temperature=-55℃~+155℃, Package=0603, Tolerance=±0.1%
R26: library part R0603_16.2KΩ_±0.1%, "100mW Thin Film Resistor 75V ±50ppm/℃ ±0.1% 16.2kΩ 0603 Chip Resistor - Surface Mount ROHS", LCSC Part=C728602, Manufacturer=YAGEO, Mfr. Part=RT0603BRE0716K2L, Operating Temperature=-55℃~+155℃, Package=0603, Tolerance=±0.1%
R27: library part R0603_133KΩ_±0.1%, "100mW Thin Film Resistor 75V ±50ppm/℃ ±0.1% 133kΩ 0603 Chip Resistor - Surface Mount ROHS", LCSC Part=C861659, Manufacturer=YAGEO, Mfr. Part=RT0603BRE07133KL, Operating Temperature=-55℃~+155℃, Package=0603, Tolerance=±0.1%
RESET: library part SW_BUTTON_SMD_3mm×4mm, "Without Bracket 50mA 4mm 100,000 Cycles 12V 1.6N 3mm 2mm Round Button Surface Mount,Vertical SPST SMD Tactile Switches ROHS", LCSC Part=C720477, Manufacturer=XUNPU, Mfr. Part=TS-1088-AR02016, Operating Temperature=-30℃~+80℃, Package=SMD, Voltage Rating=12V
RL1: "250V@AC 5V 15A 1 Form C: 1C (SPDT-CO) Through Hole,15.6x19.2mm Power Relays ROHS", Coil Voltage=5V, LCSC Part=C35449, Manufacturer="Songle Relay", Package="Through Hole,15.6x19.2mm", Switching Current(Max)=15A, Switching Voltage(Max)=250V@AC
SW1: "500mA SPDT 50V 5千次 Plugin Slide Switches ROHS", Manufacturer="SHOU HAN", Package=Plugin
T1 T2: "90V 150uA 5Ω@10V 330mW 3V@1mA 1 N-Channel SOT-23 MOSFETs ROHS", Gate Threshold Voltage (Vgs(th))=3V@1mA, LCSC Part=C151050, Manufacturer=DIODES, Package=SOT-23
TP1 TP2 TP3 TP4 TP5 TP6 TP7 TP8 TP9 TP10 TP11: library part TEST_POINT
U1: library part PIN_18650_1S_HOLDER_SMD, "Battery Holder -10℃~+100℃ Gold Phosphor Bronze Button And Strip Battery Connector ROHS", LCSC Part=C5371777, Manufacturer=MYOUNG, Mfr. Part=BH-18650-B5BA008, Package=---
U2: "Battery Holder -25℃~+85℃ Phosphor Bronze CR1220 SMD Button And Strip Battery Connector ROHS", LCSC Part=C964723, Manufacturer=MYOUNG, Mfr. Part=BS-12-B3AA003, Package=SMD
U3: "AVR 20MHz TQFP-32(7x7) Microcontrollers (MCU/MPU/SOC) ROHS", LCSC Part=C14877, Manufacturer=MICROCHIP, Package=TQFP-32(7x7), Voltage - Supply=1.8V~5.5V
U4: "8 2V~6V 1 Serial-to-Serial or Parallel TSSOP-16 Shift Registers ROHS", LCSC Part=C5948, Manufacturer=Nexperia, Mfr. Part=74HC595PW,118, Package="TSSOP16-16 Nexperia USA Inc.", Voltage - Supply=2V~6V
U5: "SO-4 Transistor, Photovoltaic Output Optoisolators ROHS", LCSC Part=C5255297, Manufacturer=TOSHIBA, Mfr. Part=TLP291(GB-TP,SE(T, Package=SO-4
U6: "Boost Adjustable 2.9V~38V 2.9V~18V 3A HTSSOP-14-EP DC-DC Converters ROHS", Frequency - Switching=2.2MHz, LCSC Part=C43276, Manufacturer=TI, Output Current=3A, Package=HTSSOP-14-EP, Voltage - Supply=2.9V~18V
X1: library part Crystal_16Mhz_HC49S, "16MHz Through Hole Crystal Oscillator 20pF ±20ppm ±30ppm HC-49S Crystals ROHS", Frequency Stability=±30ppm, LCSC Part=C16212, Load Capacitance=20pF, Manufacturer="YXC Crystal Oscillators", Mfr. Part=X49SD16MSD2SC, Operating Temperature=-20℃~+70℃, Package=HC-49S
X2: library part Crystal_32.768Khz, "32.768kHz 12.5pF ±20ppm SMD3215-2P Crystals ROHS", Frequency Stability=-, LCSC Part=C156245, Load Capacitance=12.5pF, Manufacturer=NDK, Mfr. Part=NX3215SA-32.768K-STD-MUA-8, Operating Temperature=-40℃~+85℃, Package=SMD3215-2P

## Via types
v1: diameter 23.62, hole 11.81, Top Layer to Bottom Layer, 65 vias
v2: diameter 27.56, hole 15.75, Top Layer to Bottom Layer, 11 vias
v3: diameter 24, hole 12, Top Layer to Bottom Layer, 4 vias
v4: diameter 157.48, hole 157.48, Top Layer to Bottom Layer, 3 vias

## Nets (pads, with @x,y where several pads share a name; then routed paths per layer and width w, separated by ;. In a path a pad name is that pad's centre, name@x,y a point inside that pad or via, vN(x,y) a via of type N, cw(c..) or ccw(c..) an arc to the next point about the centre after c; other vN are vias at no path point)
+3V3: C18.2 C19.2 C22.2 H5.2 IC4.2 IC5.6 R10.2 R13.2 R14.2 T1.1 T2.1 TP5.1 TP7.1 | length 4839.2
  Top Layer w10: H5.2@383.79,1815.52 460.52,1815.52 482,1837 482,2097 497,2112 v1(636,2112) ; R10.2@636,2062 v1(636,2112) ; R14.2@727,2254.35 727,2117.86 721.14,2112 v1(636,2112) ; T2.1@842.37,1991.95 v1(890,1992) v1(890,1992) ; IC5.6@1073,2345.7 1135.3,2345.7 1150,2331 1150,2234.21 1155.86,2228.35 C22.2@1184.44,2228.35 1184.44,2197.44 ; v2(1104,2184) 1171,2184 1184.44,2197.44 ; R13.2@1131,1995.04 1176.04,1995.04 1184.44,2003.44 1184.44,2197.44
  Bottom Layer w10: v1(636,2112) 874.14,2112 890,2096.14 v1(890,1992) 1074.24,1992 1104,2021.76 v2(1104,2184) 1105,2183 1320.14,2183 1326,2188.86 1326,2617 1387,2678 1776,2678 1805,2707 1805,3132 1846,3173 2647.14,3173 2653,3178.86 2653,3351.32 2648.66,3355.66 v2(2653,3360)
